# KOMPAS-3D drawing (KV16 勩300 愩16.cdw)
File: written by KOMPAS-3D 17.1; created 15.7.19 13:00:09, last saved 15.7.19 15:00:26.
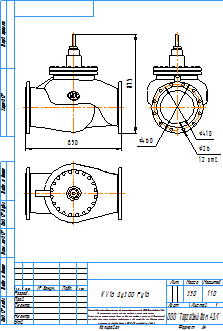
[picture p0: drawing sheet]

Sheet 1: A4, portrait

Title block, sheet 1: name: KV16 Ду300 Ру16; material: Сталь 20  ГОСТ 1050-2013; mass: 350; sheets: 1; sheet format: A4; stored path: \\adlc.lan\data\АДЛ_ПКД\3D-модели\ADL production\Вентили ГРАНВЕНТ\KV16\KOMPAS 2D\KV16 Ду300 Ру16.cdw

Views: Вид 1, Проекционный вид 2, Проекционный вид 3
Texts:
  kka
  adl
  Рама для чертежей
  Лит-Масса-Масштаб
  Материал-Предприятие
  Масштаб
  Изм.
  Лист
  № докум.
  Подп.
  Дата
  Лит.
  Разраб.
  Пров.
  Т.контр.
  Листов
  Внимание! Данный продукт является объектом авторского права ООО «Торговый Дом АДЛ».
  Запрещается изменение, копирование, распространение
  (в том числе путем копирования на другие сайты и ресурсы в Интернете)
  или любое иное использование информации и объектов без предварительного
  согласия правообладателя (ООО «Торговый Дом АДЛ»).
  Н.контр.
  Утв.
  ООО "Торговый дом АДЛ"
  Изменение
  Номер документа
  Подпись
  Обозначение документа
  Наименование изделия
  Масса изделия по ГОСТ 2.109-73
  Порядковый номер листа
  Общее количество листов в документе
  Характер работы, выполненной лицом, подписавшим документ
  Наименование или индекс предприятия, выпускающего документ
  Инв. № подл.
  Подп. и дата
  Взам. инв. №
  Инв. № дубл.
  Инвентарный номер подлинника по ГОСТ 2.501-68
  Подпись принявшего подлинник в отдел технической документации
  Инвентарный номер подлинника, взамен которого выпущен данный подлинник
  Инвентарный номер дубликата по ГОСТ 2.502-68
  Подпись принявшего дубликат в отдел технической документации
  Справ. №
  Перв. примен.
  Обозначение документа, взамен или на основании которого выпущен данный документ
  Обозначение документа, в котором впервые записан данный документ
  Подпись лица, копировавшего чертеж
  Обозначение формата листа
  !Рама для чертежа
Dimensions and other numbers on the sheet: 850; 875; 410; 460; 26; 12 отв.; 1:10; 1; 350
